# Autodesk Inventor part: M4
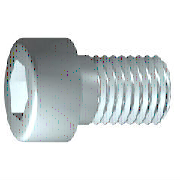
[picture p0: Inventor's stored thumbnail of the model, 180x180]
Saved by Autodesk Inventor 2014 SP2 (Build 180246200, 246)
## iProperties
IsCustomPart: 0
Company: 한국ATC센터
Created: 2014-10
Part Number: M4
Material: Steel, Mild
Description: 6각머리 태핑 나사
Document SubType Name: Modeling
Standard: KS B 1003
Designer: KYOUNG IL JANG
Standards Organization: KS
Language: ko-KR
Size Designation: M 4 x 10
Categories: <MemberInstance><Categories><Category DisplayName="조임쇠" InternalName="e4da775c-781d-43d5-af7c-5136215cf5a6" Mnemonic="FSTN"><Category DisplayName="볼트" InternalN
Density: 7.86 g/cm^3
Mass: 2.0371 g
Surface Area: 3.0572 cm^2
Volume: 0.259174 cm^3
Appearance: 검은색 캐스트
Author: KYOUNG IL JANG
Revision Number: 1
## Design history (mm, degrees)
sketch "스케치1"
  geometry: L1 (-1, 0)-(10, 0); L2 (10, 0)-(10, 2); L3 (10, 2)-(1.75, 2); L4 (1.75, 2)-(1.32, 2); L5 (1.32, 2)-(0, 2); L6 (0, 2)-(0, 3.5); L7 (0, 3.5)-(-4, 3.5); L8 (-4, 3.5)-(-4, 1.732); L9 (-4, 1.732)-(-2, 1.732); L10 (-2, 1.732)-(-1, 0); L11 (-6.8, 0)-(12.8, 0) reference; L12 (0, -0.7)-(0, 4.2) reference; L13 (1.75, 2)-(0, 2)
  constraints: 22 end point, 6 parallel, 2 collinear, 2 perpendicular, 1 horizontal, 1 point on line
  dimensions: "d1" = 8.25 distance from line of L3.end L2 (= GEL); "d2" = 0.42952 distance of L4.end L3.end (computed from GAL); "d3" = 4 distance between parallel lines of L8 L6 (= KOH); "d4" = 2 distance of L8.end L9.end (= INTI); "d5" = 60 deg angle of L10 L1; "d6" = 4 diameter of L3 L1 (= GD); "d7" = 4 diameter of L5 L1 (= BDM); "d8" = 3.4641 diameter of L9 L1 (= 1.1547 x SW); "d9" = 7 diameter of L7 L1 (= KOD); "d26" = 10 distance between parallel lines of L12 L2 (= NLG)
revolve "본체" sketch "스케치1" stored, may be unused: angle "d10" = 90 deg
sketch "스케치2"
  geometry: L1 (0, -4.9)-(0, 4.9) reference; L2 (-4.9, 0)-(4.9, 0) reference; L3 (1.732, 0)-(0.866, -1.5); L4 (0.866, -1.5)-(-0.866, -1.5); L5 (-0.866, -1.5)-(-1.732, 0); L6 (-1.732, 0)-(-0.866, 1.5); L7 (-0.866, 1.5)-(0.866, 1.5); L8 (0.866, 1.5)-(1.732, 0); 2 further points
  constraints: 12 end point, 1 coincident, 1 horizontal alignment, 1 point on line, 12 other
extrude "슬롯" join sketch "스케치2" stored distance "d11" = 10; taper "d12" = 0 deg
workplane "Work Plane1"
fillet "Fillet2" dims "d30" = 0.1 (= R)
body "Solid1"
fillet "모깎기1" dims "d17" = 0.4 (= RR)
feature "스레드" dims "d13" = 8.25 (= GEL), "d14" = 0
chamfer "모따기1" distance "d15" = 0.42941 (= -0.5 x SPD + 0.5 x GD); stored, may be unused: second distance "d16" = 0.42941 (= GUL), angle "d27" = 45 deg
other parameters: "GD" = 4 (= NND) [user parameter; used in 2 equation terms], "NLG" = 10 [user parameter; used in 1 equation term], "GEL" = 8.25 [user parameter; used in 2 equation terms], "KOD" = 7 [user parameter; used in 1 equation term], "KOH" = 4 [user parameter; used in 1 equation term], "INTI" = 2 [user parameter; used in 1 equation term], "GAL" = 0.42941 (= 0.61345 x PTC) [user parameter; used in 1 equation term], "GUL" = 0.42941 (= 0.61345 x PTC) [user parameter; used in 1 equation term], "BDM" = 4 (= NND) [user parameter; used in 1 equation term], "SW" = 3 [user parameter; used in 2 equation terms], "RR" = 0.4 [user parameter; used in 1 equation term], "SPD" = 3.14117 (= NND - 1.2269 x PTC) [user parameter; used in 1 equation term], "d19" = 0, "d28" = 0, "d29" = 0, "R" = 0.1 [user parameter; used in 1 equation term], "PHH" = 0.2 [user parameter], "GD1" = 3.14117 (= THREADDIA - 1.2269 x PTC) [user parameter], "THREADDIA" = 4 [user parameter; used in 1 equation term], "FAWI" = 45 deg [user parameter], "TPU" = 14.28571 (computed from PTC) [user parameter], "PTC" = 0.7 [user parameter; used in 5 equation terms], "NND" = 4 [user parameter; used in 3 equation terms], "TOA" = 30 deg [user parameter], "E0" = 3.465 (= 1.155 x SW) [user parameter]
